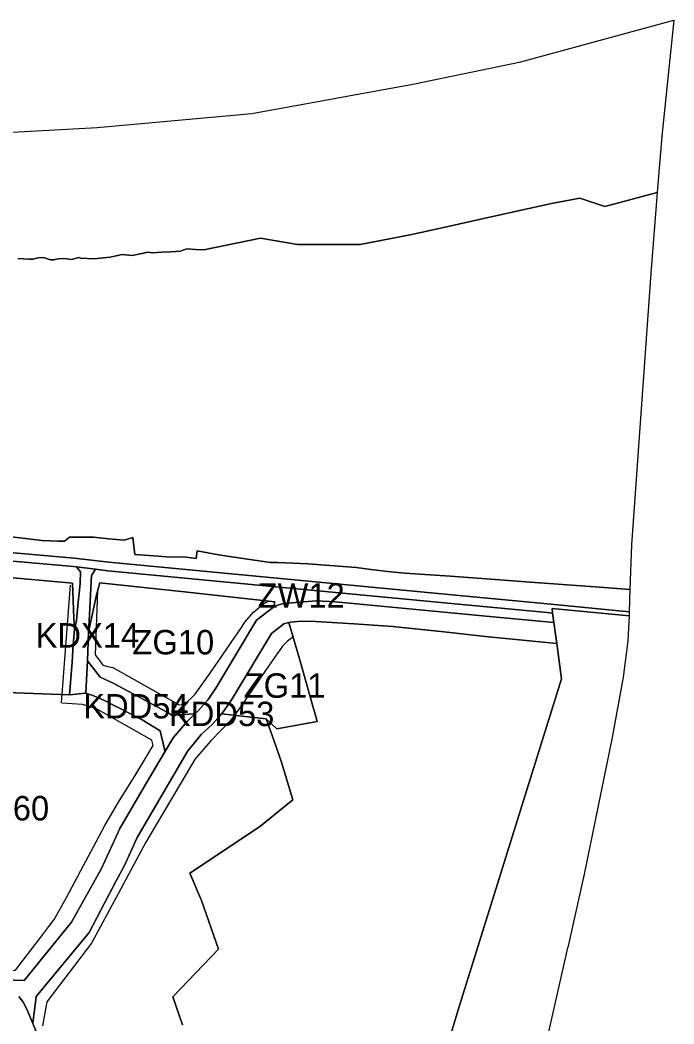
# Model space of a CAD drawing. Extents: x 7428841 to 7433518, y 5545054 to 5546840.
# Drawn here: x 7433230.3 to 7433497.8, y 5546084.6 to 5546495.4 of the extents above; entities that cross this region are included whole.
import ezdxf

# ---------------------------------------------------------------- set-up
doc = ezdxf.new("R2010")
doc.units = 0
for name, color, linetype in [('linie_rozgraniczajace', 7, 'Continuous'), ('linie_zabudowy_nieprzekraczalne', 7, 'Continuous'), ('oznaczenia_przeznaczen', 7, 'Continuous')]:
    doc.layers.add(name, color=color, linetype=linetype)

msp = doc.modelspace()

# ---------------------------------------------------------------- linework, layer by layer
at = {"layer": 'linie_rozgraniczajace'}
for points in [[(7433192.29, 5546447.64), (7433261.86, 5546451.37), (7433325.2, 5546457.14), (7433390.96, 5546469.21), (7433435.13, 5546478.26), (7433497.78, 5546495.38), (7433492.87, 5546447.86), (7433490.99, 5546424.78), (7433469.57, 5546419.14), (7433459.28, 5546422.57), (7433448.33, 5546420.4), (7433432.78, 5546417.03), (7433415.16, 5546413.08), (7433404.26, 5546410.61), (7433389.95, 5546407.48), (7433369.38, 5546403.52), (7433343.83, 5546403.53), (7433328.67, 5546406.07), (7433305.53, 5546401.34), (7433302.14, 5546401.56), (7433298.75, 5546401.77), (7433297.39, 5546401.32), (7433296.02, 5546400.87), (7433291.91, 5546400.6), (7433288.14, 5546400.35), (7433284.37, 5546400.1), (7433282.7, 5546400.37), (7433276.14, 5546399.06), (7433272.11, 5546399.48), (7433267.23, 5546398.34), (7433260.46, 5546397.67), (7433255.21, 5546397.93), (7433254.56, 5546398.16), (7433252.87, 5546397.78), (7433251.19, 5546397.39), (7433248.6, 5546397.85), (7433246.24, 5546397.71), (7433245.18, 5546397.51), (7433244.13, 5546397.31), (7433243.49, 5546397.27), (7433242.86, 5546397.24), (7433241.84, 5546397.61), (7433240.82, 5546397.98), (7433240.2, 5546398.12), (7433239.58, 5546398.26), (7433237.68, 5546398.07), (7433236.61, 5546397.81), (7433235.54, 5546397.55), (7433234.17, 5546397.59), (7433231.77, 5546397.67), (7433229.37, 5546397.75)], [(7433252.87, 5546397.78), (7433254.56, 5546398.16), (7433255.21, 5546397.93), (7433260.46, 5546397.67), (7433267.23, 5546398.34), (7433272.11, 5546399.48), (7433276.14, 5546399.06), (7433282.7, 5546400.37), (7433284.37, 5546400.1), (7433288.14, 5546400.35), (7433291.91, 5546400.6), (7433296.02, 5546400.87), (7433297.39, 5546401.32), (7433298.75, 5546401.77), (7433302.14, 5546401.56), (7433305.53, 5546401.34), (7433328.67, 5546406.07), (7433343.83, 5546403.53), (7433369.38, 5546403.52), (7433389.95, 5546407.48), (7433404.26, 5546410.61), (7433415.16, 5546413.08), (7433432.78, 5546417.03), (7433448.33, 5546420.4), (7433459.28, 5546422.57), (7433469.57, 5546419.14), (7433490.99, 5546424.78), (7433488.3, 5546391.83), (7433480.43, 5546280.69), (7433479.8, 5546262.32), (7433465.54, 5546263.48), (7433438.92, 5546265.33), (7433426.57, 5546266.39), (7433406.21, 5546267.85), (7433387.65, 5546269.1), (7433380.74, 5546269.79), (7433373.83, 5546270.49), (7433367.8, 5546271.43), (7433348.13, 5546272.81), (7433335.69, 5546273.42), (7433332.81, 5546273.39), (7433323.4, 5546274.79), (7433311.57, 5546276.57), (7433302.77, 5546278.22), (7433302.37, 5546275.1), (7433297.21, 5546275.76), (7433292.02, 5546275.61), (7433284.91, 5546276.14), (7433281.08, 5546276.41), (7433277.26, 5546276.68), (7433276.52, 5546283.61), (7433272.94, 5546282.58), (7433266.65, 5546283.15), (7433260.36, 5546283.72), (7433250.57, 5546283.76), (7433248.54, 5546282.15), (7433245.77, 5546282.21), (7433239.3, 5546282.37), (7433233.67, 5546283.05), (7433219.69, 5546284.79)], [(7433229.37, 5546397.75), (7433231.77, 5546397.67), (7433234.17, 5546397.59), (7433235.54, 5546397.55), (7433236.61, 5546397.81), (7433237.68, 5546398.07), (7433239.58, 5546398.26), (7433240.2, 5546398.12), (7433240.82, 5546397.98), (7433241.84, 5546397.61), (7433242.86, 5546397.24), (7433243.49, 5546397.27), (7433244.13, 5546397.31), (7433245.18, 5546397.51), (7433246.24, 5546397.71), (7433248.6, 5546397.85), (7433251.19, 5546397.39), (7433252.87, 5546397.78)], [(7433219.69, 5546284.79), (7433233.67, 5546283.05), (7433239.3, 5546282.37), (7433245.77, 5546282.21), (7433248.54, 5546282.15), (7433250.57, 5546283.76), (7433260.36, 5546283.72), (7433266.65, 5546283.15), (7433272.94, 5546282.58), (7433276.52, 5546283.61), (7433277.26, 5546276.68), (7433281.08, 5546276.41), (7433284.91, 5546276.14), (7433292.02, 5546275.61), (7433297.21, 5546275.76), (7433302.37, 5546275.1), (7433302.77, 5546278.22), (7433311.57, 5546276.57), (7433323.4, 5546274.79), (7433332.81, 5546273.39), (7433335.69, 5546273.42), (7433348.13, 5546272.81), (7433367.8, 5546271.43), (7433373.83, 5546270.49), (7433380.74, 5546269.79), (7433387.65, 5546269.1), (7433406.21, 5546267.85), (7433426.57, 5546266.39), (7433438.92, 5546265.33), (7433465.54, 5546263.48), (7433479.8, 5546262.32), (7433479.49, 5546253.28), (7433446.14, 5546256.46), (7433412.8, 5546259.64), (7433339.71, 5546266.59), (7433266.62, 5546273.54), (7433252.5, 5546275.21), (7433230.83, 5546277.11), (7433209.16, 5546279)], [(7433209.16, 5546279), (7433230.83, 5546277.11), (7433252.5, 5546275.21), (7433266.62, 5546273.54), (7433339.71, 5546266.59), (7433412.8, 5546259.64), (7433446.14, 5546256.46), (7433479.49, 5546253.28), (7433479.42, 5546251.53), (7433447.93, 5546254.57), (7433448.18, 5546252.75), (7433445.91, 5546252.97), (7433412.47, 5546256.16), (7433339.36, 5546263.11), (7433266.26, 5546270.06), (7433261.19, 5546270.66), (7433253.43, 5546271.58), (7433252.15, 5546271.73), (7433230.5, 5546273.63), (7433208.84, 5546275.52)], [(7433224.39, 5546102.64), (7433232.08, 5546102.4), (7433251.34, 5546126.25), (7433263.63, 5546148.19), (7433271.11, 5546164.55), (7433280.32, 5546180.22), (7433289.53, 5546195.89), (7433292.99, 5546201.65), (7433298.64, 5546208.37), (7433301.8, 5546211.49), (7433303.19, 5546212.75), (7433307.26, 5546217.36), (7433310.42, 5546221.97), (7433318.76, 5546235.89), (7433327.1, 5546249.81), (7433333.95, 5546255.15), (7433334.7, 5546255.74), (7433337.67, 5546256.46), (7433343.01, 5546257.11), (7433351.49, 5546257.74), (7433359.34, 5546257.31), (7433390.86, 5546254.32), (7433422.38, 5546251.33), (7433448.72, 5546248.83), (7433449.89, 5546240.26), (7433422, 5546243), (7433402.41, 5546245.12), (7433384.09, 5546247.09), (7433382.82, 5546247.24), (7433367.03, 5546248.26), (7433351.24, 5546249.29), (7433345.18, 5546249.39), (7433340.99, 5546249.03), (7433340.27, 5546248.86), (7433338.26, 5546248.37), (7433333.2, 5546244.42), (7433325.17, 5546231.04), (7433317.16, 5546217.66), (7433313.59, 5546212.43), (7433312.74, 5546211.47), (7433311.24, 5546209.77), (7433308.89, 5546207.12), (7433304.4, 5546203.06), (7433301.68, 5546199.68), (7433298.96, 5546196.31), (7433288.59, 5546178.58), (7433278.22, 5546160.85), (7433273, 5546149.46), (7433269.6, 5546143.1), (7433258.54, 5546122.01), (7433236.98, 5546095.76), (7433235.71, 5546085.88), (7433235.57, 5546084.76), (7433233.28, 5546090.32), (7433232.06, 5546092.68), (7433231.75, 5546093.31), (7433229.88, 5546095.77)], [(7433400.97, 5546061.74), (7433409.6, 5546090.32), (7433451.77, 5546225.75), (7433449.89, 5546240.26), (7433448.72, 5546248.83), (7433448.18, 5546252.75), (7433447.93, 5546254.57), (7433479.42, 5546251.53), (7433478.97, 5546241.42), (7433476.99, 5546226.53), (7433472.55, 5546201.77), (7433461.08, 5546145.83), (7433454.34, 5546115.86), (7433454.3, 5546115.72), (7433443.19, 5546066.88)], [(7433296.79, 5546084.2), (7433292.83, 5546095.75), (7433311.5, 5546115.2), (7433304.58, 5546135.1), (7433299.83, 5546146.3), (7433328.34, 5546165.22), (7433341.93, 5546176.24), (7433338.87, 5546186.22), (7433337.22, 5546191.65), (7433334.08, 5546200.71), (7433331, 5546209.46), (7433335.3, 5546205.31), (7433351.8, 5546208.32), (7433351.26, 5546210.41), (7433350.15, 5546214.69), (7433344.86, 5546233), (7433340.27, 5546248.86), (7433340.99, 5546249.03), (7433345.18, 5546249.39), (7433351.24, 5546249.29), (7433367.03, 5546248.26), (7433382.82, 5546247.24), (7433384.09, 5546247.09), (7433402.41, 5546245.12), (7433422, 5546243), (7433449.89, 5546240.26), (7433451.77, 5546225.75), (7433409.6, 5546090.32), (7433400.97, 5546061.74)], [(7433209.98, 5546220.72), (7433250.57, 5546219.26), (7433257.26, 5546219.94), (7433260.13, 5546219.03), (7433264.88, 5546216.91), (7433280.25, 5546209.01), (7433287.62, 5546204.6), (7433289.41, 5546196.98), (7433289.53, 5546195.89), (7433280.32, 5546180.22), (7433271.11, 5546164.55), (7433263.63, 5546148.19), (7433251.34, 5546126.25), (7433232.08, 5546102.4), (7433224.39, 5546102.64)], [(7433237.21, 5546080.78), (7433235.57, 5546084.76), (7433235.71, 5546085.88), (7433236.98, 5546095.76), (7433258.54, 5546122.01), (7433269.6, 5546143.1), (7433273, 5546149.46), (7433278.22, 5546160.85), (7433288.59, 5546178.58), (7433298.96, 5546196.31), (7433301.68, 5546199.68), (7433304.4, 5546203.06), (7433308.89, 5546207.12), (7433311.24, 5546209.77), (7433312.74, 5546211.47), (7433331, 5546209.46), (7433334.08, 5546200.71), (7433337.22, 5546191.65), (7433338.87, 5546186.22), (7433341.93, 5546176.24), (7433328.34, 5546165.22), (7433299.83, 5546146.3), (7433304.58, 5546135.1), (7433311.5, 5546115.2), (7433292.83, 5546095.75), (7433296.79, 5546084.2)], [(7433229.88, 5546095.77), (7433231.75, 5546093.31), (7433232.06, 5546092.68), (7433233.28, 5546090.32), (7433235.57, 5546084.76), (7433237.21, 5546080.78)]]:
    msp.add_lwpolyline(points, dxfattribs=at)
for points in [[(7433113.77, 5546284.91), (7433136.65, 5546282.81), (7433172.74, 5546279.17), (7433208.84, 5546275.52), (7433230.5, 5546273.63), (7433252.15, 5546271.73), (7433253.43, 5546271.58), (7433255.12, 5546269.63), (7433254.95, 5546265.01), (7433254.48, 5546260.79), (7433254.25, 5546258.49), (7433253.62, 5546251.37), (7433253.4, 5546249.53), (7433252.54, 5546245.99), (7433252.35, 5546250.6), (7433251.8, 5546264.94), (7433221.23, 5546267.73), (7433194.42, 5546270.18), (7433171.16, 5546272.36), (7433119.54, 5546278.87), (7433117.27, 5546265.37)], [(7433117.27, 5546265.37), (7433119.54, 5546278.87), (7433171.16, 5546272.36), (7433194.42, 5546270.18), (7433221.23, 5546267.73), (7433251.8, 5546264.94), (7433252.35, 5546250.6), (7433252.54, 5546245.99), (7433252.12, 5546239.8), (7433251.58, 5546232.64), (7433250.57, 5546219.26), (7433209.98, 5546220.72), (7433206.76, 5546208.86), (7433190.86, 5546213.73), (7433177.54, 5546217.71), (7433155.69, 5546229.21), (7433151.7, 5546227.97), (7433146.94, 5546234.85), (7433144.44, 5546236.45), (7433128.87, 5546245.38), (7433125.22, 5546248.37), (7433121.64, 5546252.01), (7433119.2, 5546256.34), (7433118.51, 5546259.28)], [(7433250.57, 5546219.26), (7433251.58, 5546232.64), (7433252.12, 5546239.8), (7433252.54, 5546245.99), (7433253.4, 5546249.53), (7433253.62, 5546251.37), (7433254.25, 5546258.49), (7433254.48, 5546260.79), (7433254.95, 5546265.01), (7433255.12, 5546269.63), (7433253.43, 5546271.58), (7433261.19, 5546270.66), (7433259.5, 5546268.1), (7433259.24, 5546262.9), (7433258.68, 5546251.82), (7433258.39, 5546244.97), (7433257.95, 5546233.14), (7433257.26, 5546219.94)], [(7433258.39, 5546244.97), (7433258.68, 5546251.82), (7433259.24, 5546262.9), (7433259.5, 5546268.1), (7433261.19, 5546270.66), (7433266.26, 5546270.06), (7433339.36, 5546263.11), (7433412.47, 5546256.16), (7433445.91, 5546252.97), (7433448.18, 5546252.75), (7433448.72, 5546248.83), (7433422.38, 5546251.33), (7433390.86, 5546254.32), (7433359.34, 5546257.31), (7433351.49, 5546257.74), (7433343.01, 5546257.11), (7433337.67, 5546256.46), (7433334.7, 5546255.74), (7433333.95, 5546255.15), (7433334.58, 5546257.29), (7433298.77, 5546261.22), (7433262.96, 5546265.15), (7433261.65, 5546260.23)], [(7433257.95, 5546233.14), (7433258.39, 5546244.97), (7433261.65, 5546260.23), (7433262.96, 5546265.15), (7433298.77, 5546261.22), (7433334.58, 5546257.29), (7433333.95, 5546255.15), (7433327.1, 5546249.81), (7433318.76, 5546235.89), (7433310.42, 5546221.97), (7433307.26, 5546217.36), (7433303.19, 5546212.75), (7433301.8, 5546211.49), (7433297.21, 5546211.16), (7433292.61, 5546210.82), (7433291.43, 5546211.67), (7433279.92, 5546217.88), (7433268.41, 5546224.09), (7433263.04, 5546226.49)], [(7433312.74, 5546211.47), (7433313.59, 5546212.43), (7433317.16, 5546217.66), (7433325.17, 5546231.04), (7433333.2, 5546244.42), (7433338.26, 5546248.37), (7433340.27, 5546248.86), (7433344.86, 5546233), (7433350.15, 5546214.69), (7433351.26, 5546210.41), (7433351.8, 5546208.32), (7433335.3, 5546205.31), (7433331, 5546209.46)], [(7433257.26, 5546219.94), (7433257.95, 5546233.14), (7433263.04, 5546226.49), (7433268.41, 5546224.09), (7433279.92, 5546217.88), (7433291.43, 5546211.67), (7433292.61, 5546210.82), (7433297.21, 5546211.16), (7433301.8, 5546211.49), (7433298.64, 5546208.37), (7433292.99, 5546201.65), (7433289.53, 5546195.89), (7433289.41, 5546196.98), (7433287.62, 5546204.6), (7433280.25, 5546209.01), (7433264.88, 5546216.91), (7433260.13, 5546219.03)]]:
    msp.add_lwpolyline(points, close=True, dxfattribs=at)
at = {"layer": 'linie_zabudowy_nieprzekraczalne'}
for points in [[(7433247.34, 5546215.99), (7433250.94, 5546264.19)], [(7433261.98, 5546261.82), (7433261.06, 5546235.61)], [(7433321.19, 5546247.26), (7433322.34, 5546248.96), (7433325.86, 5546253.06), (7433330.08, 5546256.7), (7433331.69, 5546257.55)], [(7433297.64, 5546215.25), (7433301.97, 5546219.52), (7433308.38, 5546228.52), (7433321.19, 5546247.26)], [(7433342.32, 5546243.08), (7433339.67, 5546241.2), (7433337.66, 5546239.17), (7433331.93, 5546230.99), (7433320.87, 5546214.93), (7433316.52, 5546208.86), (7433308.32, 5546200.49), (7433301.9, 5546193.06), (7433281.77, 5546159.01), (7433270.55, 5546138.07), (7433259.5, 5546117.66), (7433241.25, 5546093.66), (7433239.56, 5546083.82)], [(7433261.09, 5546235.63), (7433262.03, 5546234.36)], [(7433262.03, 5546234.36), (7433264.22, 5546231.41), (7433266.25, 5546230.92)], [(7433266.25, 5546230.92), (7433268.28, 5546230.42), (7433295.36, 5546215.15), (7433297.64, 5546215.25)], [(7433284.77, 5546198.59), (7433284.24, 5546200.72), (7433261.26, 5546213.72), (7433255.93, 5546215.35), (7433247.36, 5546215.88)], [(7433277.78, 5546186.95), (7433284.77, 5546198.59)], [(7433194, 5546131.45), (7433204.01, 5546125.67), (7433211.88, 5546119.54), (7433219.74, 5546113.4), (7433226.62, 5546106.5), (7433228.47, 5546106.54), (7433239.67, 5546121.13), (7433242.09, 5546124.41), (7433244.28, 5546127.35), (7433249.29, 5546136.27), (7433255.13, 5546147.38), (7433261.51, 5546159.11), (7433264.96, 5546165.82), (7433270.61, 5546175.32), (7433277.78, 5546186.95)]]:
    msp.add_lwpolyline(points, dxfattribs=at)

# ---------------------------------------------------------------- texts
at = {"layer": 'oznaczenia_przeznaczen'}
for s, p in [('ZW12', (7433327.49, 5546254.96)), ('KDX14', (7433236.7, 5546238.6)), ('ZG10', (7433276.3, 5546235.82)), ('ZG11', (7433321.81, 5546218.06)), ('KDD54', (7433256.18, 5546209.61)), ('KDD53', (7433291.24, 5546206.47)), ('MN60', (7433206.57, 5546167.88))]:
    msp.add_text(s, height=10, dxfattribs=at).set_placement(p)

doc.saveas('drawing.dxf')
